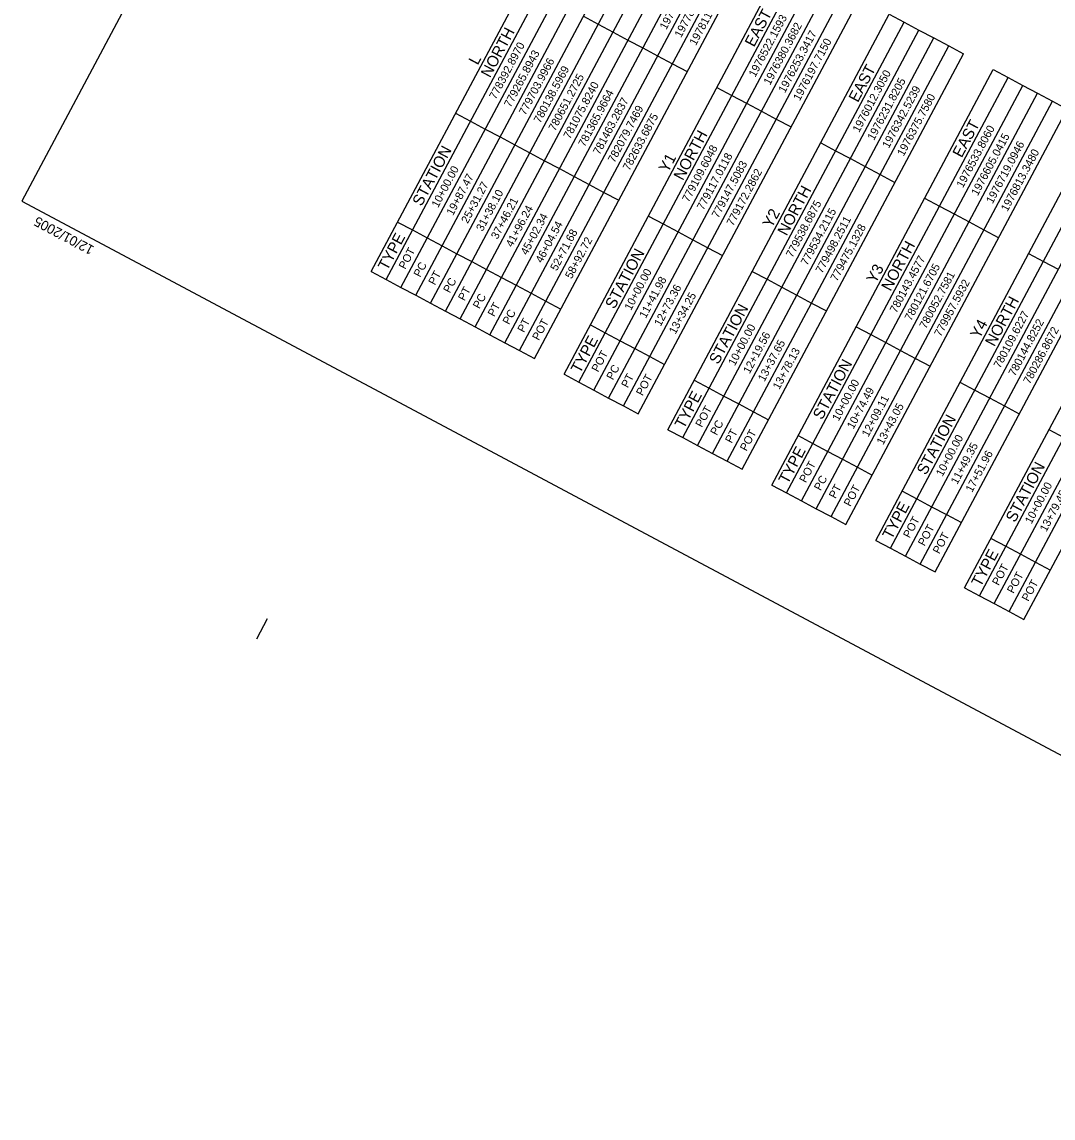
# Model space of a CAD drawing. Extents: x 1979034 to 1987549, y 771535 to 781988.
# Drawn here: x 1979034 to 1981933, y 772365 to 775446 of the extents above; entities that cross this region are included whole.
import ezdxf

# ---------------------------------------------------------------- set-up
doc = ezdxf.new("R2010")
doc.units = 0
for name, color, linetype in [('CTL Sheet Border CELL', 7, 'Continuous'), ('CTL Sheet Notes CELL', 7, 'Continuous'), ('CTL Sheet Table Cell', 7, 'Continuous'), ('CTL Sheet Text', 7, 'Continuous'), ('Sheet Data Field CELL', 7, 'Continuous')]:
    doc.layers.add(name, color=color, linetype=linetype)

msp = doc.modelspace()

# ---------------------------------------------------------------- linework, layer by layer
at = {"layer": 'CTL Sheet Border CELL'}
msp.add_lwpolyline([(1982714.7, 781848.1), (1979034.2, 774941.4), (1983868.8, 772365.1), (1987549.3, 779271.7)], close=True, dxfattribs=at)
at = {"layer": 'CTL Sheet Table Cell'}
for p, q in [((1980016.2, 774744.1), (1980638.4, 775911.6)), ((1980057.9, 774721.8), (1980680.1, 775889.4)), ((1980099.6, 774699.6), (1980721.8, 775867.2)), ((1980141.3, 774677.4), (1980763.5, 775845)), ((1980183, 774655.2), (1980805.2, 775822.8)), ((1980224.7, 774633), (1980846.9, 775800.5)), ((1980266.4, 774610.7), (1980888.6, 775778.3)), ((1980308.1, 774588.5), (1980930.3, 775756.1)), ((1980349.8, 774566.3), (1980972, 775733.9)), ((1980391.5, 774544.1), (1981013.7, 775711.6)), ((1980433.2, 774521.9), (1981055.4, 775689.4)), ((1980474.9, 774499.6), (1981097.1, 775667.2)), ((1980558.3, 774455.2), (1981180.5, 775622.8)), ((1980600, 774433), (1981222.2, 775600.5)), ((1980641.7, 774410.8), (1981263.9, 775578.3)), ((1980683.4, 774388.5), (1981305.6, 775556.1)), ((1980725.1, 774366.3), (1981347.3, 775533.9)), ((1980766.8, 774344.1), (1981389, 775511.7)), ((1980612.6, 775461.4), (1980654.3, 775439.1)), ((1980850.2, 774299.6), (1981472.4, 775467.2)), ((1980891.9, 774277.4), (1981514.1, 775445)), ((1981472.4, 775467.2), (1981514.1, 775445)), ((1981514.1, 775445), (1981555.8, 775422.8)), ((1980654.3, 775439.1), (1980696, 775416.9)), ((1980696, 775416.9), (1980737.7, 775394.7)), ((1980933.6, 774255.2), (1981555.8, 775422.8)), ((1981555.8, 775422.8), (1981597.5, 775400.6)), ((1980737.7, 775394.7), (1980779.4, 775372.5)), ((1980975.3, 774233), (1981597.5, 775400.6)), ((1981597.5, 775400.6), (1981639.2, 775378.3)), ((1980779.4, 775372.5), (1980821.1, 775350.3)), ((1981017, 774210.8), (1981639.2, 775378.3)), ((1981058.7, 774188.5), (1981680.9, 775356.1)), ((1981639.2, 775378.3), (1981680.9, 775356.1)), ((1980821.1, 775350.3), (1980862.8, 775328)), ((1980862.8, 775328), (1980904.5, 775305.8)), ((1981142.1, 774144.1), (1981764.3, 775311.7)), ((1981764.3, 775311.7), (1981806, 775289.4)), ((1980987.9, 775261.4), (1981029.6, 775239.2)), ((1981183.8, 774121.9), (1981806, 775289.4)), ((1981225.5, 774099.7), (1981847.7, 775267.2)), ((1981806, 775289.4), (1981847.7, 775267.2)), ((1981847.7, 775267.2), (1981889.3, 775245)), ((1981029.6, 775239.2), (1981071.3, 775216.9)), ((1981267.2, 774077.4), (1981889.3, 775245)), ((1981889.3, 775245), (1981931, 775222.8)), ((1981071.3, 775216.9), (1981113, 775194.7)), ((1981308.9, 774055.2), (1981931, 775222.8)), ((1981350.6, 774033), (1981972.7, 775200.6)), ((1981931, 775222.8), (1981972.7, 775200.6)), ((1980253.2, 775188.9), (1980294.9, 775166.6)), ((1981113, 775194.7), (1981154.7, 775172.5)), ((1981154.7, 775172.5), (1981196.4, 775150.3)), ((1980294.9, 775166.6), (1980336.6, 775144.4)), ((1980336.6, 775144.4), (1980378.3, 775122.2)), ((1981434, 773988.6), (1982056.1, 775156.1)), ((1980378.3, 775122.2), (1980420, 775100)), ((1981475.7, 773966.3), (1982097.8, 775133.9)), ((1981517.4, 773944.1), (1982139.5, 775111.7)), ((1980420, 775100), (1980461.7, 775077.8)), ((1980461.7, 775077.8), (1980503.4, 775055.5)), ((1981279.8, 775105.8), (1981321.5, 775083.6)), ((1981321.5, 775083.6), (1981363.2, 775061.4)), ((1981559.1, 773921.9), (1982181.2, 775089.5)), ((1980503.4, 775055.5), (1980545.1, 775033.3)), ((1981363.2, 775061.4), (1981404.9, 775039.2)), ((1981600.8, 773899.7), (1982222.9, 775067.2)), ((1980545.1, 775033.3), (1980586.8, 775011.1)), ((1981404.9, 775039.2), (1981446.6, 775016.9)), ((1981446.6, 775016.9), (1981488.3, 774994.7)), ((1981684.1, 773855.2), (1982306.3, 775022.8)), ((1980586.8, 775011.1), (1980628.5, 774988.9)), ((1980628.5, 774988.9), (1980670.2, 774966.6)), ((1981725.8, 773833), (1982348, 775000.6)), ((1980670.2, 774966.6), (1980711.9, 774944.4)), ((1981767.5, 773810.8), (1982389.7, 774978.4)), ((1981809.2, 773788.6), (1982431.4, 774956.1)), ((1981571.7, 774950.3), (1981613.4, 774928.1)), ((1981613.4, 774928.1), (1981655.1, 774905.8)), ((1981850.9, 773766.3), (1982473.1, 774933.9)), ((1980795.3, 774900), (1980837, 774877.8)), ((1981655.1, 774905.8), (1981696.8, 774883.6)), ((1980090.3, 774883.1), (1980132, 774860.8)), ((1980132, 774860.8), (1980173.7, 774838.6)), ((1980837, 774877.8), (1980878.7, 774855.5)), ((1981696.8, 774883.6), (1981738.5, 774861.4)), ((1981738.5, 774861.4), (1981780.2, 774839.2)), ((1980173.7, 774838.6), (1980215.4, 774816.4)), ((1980878.7, 774855.5), (1980920.4, 774833.3)), ((1980920.4, 774833.3), (1980962.1, 774811.1)), ((1980215.4, 774816.4), (1980257.1, 774794.2)), ((1980962.1, 774811.1), (1981003.8, 774788.9)), ((1980257.1, 774794.2), (1980298.8, 774772)), ((1980298.8, 774772), (1980340.5, 774749.7)), ((1981863.6, 774794.7), (1981905.3, 774772.5)), ((1981905.3, 774772.5), (1981947, 774750.3)), ((1980016.2, 774744.1), (1980057.9, 774721.8)), ((1980340.5, 774749.7), (1980382.2, 774727.5)), ((1981087.2, 774744.4), (1981128.9, 774722.2)), ((1980057.9, 774721.8), (1980099.6, 774699.6)), ((1980382.2, 774727.5), (1980423.9, 774705.3)), ((1981128.9, 774722.2), (1981170.6, 774700)), ((1980099.6, 774699.6), (1980141.3, 774677.4)), ((1980141.3, 774677.4), (1980183, 774655.2)), ((1980423.9, 774705.3), (1980465.6, 774683.1)), ((1980465.6, 774683.1), (1980507.3, 774660.9)), ((1981170.6, 774700), (1981212.3, 774677.8)), ((1981212.3, 774677.8), (1981254, 774655.6)), ((1980183, 774655.2), (1980224.7, 774633)), ((1980507.3, 774660.9), (1980549, 774638.6)), ((1981254, 774655.6), (1981295.7, 774633.3)), ((1980224.7, 774633), (1980266.4, 774610.7)), ((1980266.4, 774610.7), (1980308.1, 774588.5)), ((1980308.1, 774588.5), (1980349.8, 774566.3)), ((1980632.4, 774594.2), (1980674, 774572)), ((1981379.1, 774588.9), (1981420.8, 774566.7)), ((1980349.8, 774566.3), (1980391.5, 774544.1)), ((1980674, 774572), (1980715.7, 774549.7)), ((1981420.8, 774566.7), (1981462.5, 774544.4)), ((1980391.5, 774544.1), (1980433.2, 774521.9)), ((1980433.2, 774521.9), (1980474.9, 774499.6)), ((1980715.7, 774549.7), (1980757.4, 774527.5)), ((1980757.4, 774527.5), (1980799.1, 774505.3)), ((1981462.5, 774544.4), (1981504.2, 774522.2)), ((1981504.2, 774522.2), (1981545.9, 774500)), ((1980799.1, 774505.3), (1980840.8, 774483.1)), ((1981545.9, 774500), (1981587.6, 774477.8)), ((1980558.3, 774455.2), (1980600, 774433)), ((1980600, 774433), (1980641.7, 774410.8)), ((1980924.2, 774438.6), (1980965.9, 774416.4)), ((1981671, 774433.3), (1981712.7, 774411.1)), ((1980641.7, 774410.8), (1980683.4, 774388.5)), ((1980965.9, 774416.4), (1981007.6, 774394.2)), ((1981712.7, 774411.1), (1981754.4, 774388.9)), ((1980683.4, 774388.5), (1980725.1, 774366.3)), ((1981007.6, 774394.2), (1981049.3, 774372)), ((1981049.3, 774372), (1981091, 774349.8)), ((1981754.4, 774388.9), (1981796.1, 774366.7)), ((1981796.1, 774366.7), (1981837.8, 774344.5)), ((1980725.1, 774366.3), (1980766.8, 774344.1)), ((1981091, 774349.8), (1981132.7, 774327.5)), ((1980850.2, 774299.6), (1980891.9, 774277.4)), ((1980891.9, 774277.4), (1980933.6, 774255.2)), ((1981216.1, 774283.1), (1981257.8, 774260.9)), ((1981921.2, 774300), (1981962.9, 774277.8)), ((1980933.6, 774255.2), (1980975.3, 774233)), ((1981257.8, 774260.9), (1981299.5, 774238.7)), ((1980975.3, 774233), (1981017, 774210.8)), ((1981299.5, 774238.7), (1981341.2, 774216.4)), ((1981341.2, 774216.4), (1981382.9, 774194.2)), ((1981017, 774210.8), (1981058.7, 774188.5)), ((1981382.9, 774194.2), (1981424.6, 774172)), ((1981142.1, 774144.1), (1981183.8, 774121.9)), ((1981183.8, 774121.9), (1981225.5, 774099.7)), ((1981508, 774127.5), (1981549.7, 774105.3)), ((1981225.5, 774099.7), (1981267.2, 774077.4)), ((1981549.7, 774105.3), (1981591.4, 774083.1)), ((1981267.2, 774077.4), (1981308.9, 774055.2)), ((1981591.4, 774083.1), (1981633.1, 774060.9)), ((1981633.1, 774060.9), (1981674.8, 774038.7)), ((1981308.9, 774055.2), (1981350.6, 774033)), ((1981434, 773988.6), (1981475.7, 773966.3)), ((1981475.7, 773966.3), (1981517.4, 773944.1)), ((1981758.2, 773994.2), (1981799.9, 773972)), ((1981799.9, 773972), (1981841.6, 773949.8)), ((1981517.4, 773944.1), (1981559.1, 773921.9)), ((1981841.6, 773949.8), (1981883.3, 773927.6)), ((1981559.1, 773921.9), (1981600.8, 773899.7)), ((1981883.3, 773927.6), (1981925, 773905.3)), ((1981684.1, 773855.2), (1981725.8, 773833)), ((1981725.8, 773833), (1981767.5, 773810.8)), ((1981767.5, 773810.8), (1981809.2, 773788.6)), ((1981809.2, 773788.6), (1981850.9, 773766.3))]:
    msp.add_line(p, q, dxfattribs=at)
at = {"layer": 'Sheet Data Field CELL'}
msp.add_line((1979694.3, 773711.8), (1979724.9, 773769.3), dxfattribs=at)

# ---------------------------------------------------------------- texts
at = {"layer": 'CTL Sheet Notes CELL'}
for s, p in [('EAST', (1981092, 775373)), ('NORTH', (1980350, 775286.7)), ('L', (1980315.4, 775322.4)), ('EAST', (1981383.9, 775217.4)), ('EAST', (1981675.8, 775061.9)), ('NORTH', (1980892.1, 774997.8)), ('STATION', (1980157.5, 774925.5)), ('Y1', (1980850.2, 775019.7)), ('NORTH', (1981183.9, 774842.3)), ('Y2', (1981142.1, 774864.2)), ('TYPE', (1980061, 774744.5)), ('NORTH', (1981475.8, 774686.7)), ('STATION', (1980699.6, 774636.6)), ('Y3', (1981434, 774708.6)), ('NORTH', (1981767.7, 774531.2)), ('STATION', (1980991.5, 774481.1)), ('Y4', (1981725.9, 774553.1)), ('TYPE', (1980603.1, 774455.6)), ('STATION', (1981283.4, 774325.5)), ('TYPE', (1980895, 774300.1)), ('STATION', (1981575.3, 774170)), ('TYPE', (1981186.9, 774144.5)), ('STATION', (1981825.5, 774036.7)), ('TYPE', (1981478.8, 773989)), ('TYPE', (1981729, 773855.6))]:
    msp.add_text(s, height=31.5, rotation=61.9471, dxfattribs=at).set_placement(p)
at = {"layer": 'CTL Sheet Text'}
for s, p in [('1977585.8266', (1980845.2, 775421.9)), ('1977839.0293', (1980886.9, 775399.6)), ('1978119.8182', (1980928.6, 775377.4)), ('1976522.1593', (1981095.4, 775288.5)), ('1976380.3682', (1981137.1, 775266.3)), ('1976253.3417', (1981178.8, 775244.1)), ('778392.8970', (1980366, 775225.9)), ('1976197.7150', (1981220.5, 775221.9)), ('779265.8943', (1980407.7, 775203.6)), ('779703.9966', (1980449.4, 775181.4)), ('780138.5969', (1980491.1, 775159.2)), ('780651.2725', (1980532.8, 775137)), ('1976012.3050', (1981387.3, 775133)), ('781075.8240', (1980574.5, 775114.8)), ('1976231.8205', (1981429, 775110.8)), ('1976342.5239', (1981470.7, 775088.5)), ('781365.9664', (1980616.2, 775092.5)), ('781463.2837', (1980657.9, 775070.3)), ('1976375.7580', (1981512.4, 775066.3)), ('782079.7469', (1980699.6, 775048.1)), ('782633.6875', (1980741.3, 775025.9)), ('1976533.8060', (1981679.2, 774977.4)), ('1976605.0415', (1981720.9, 774955.2)), ('1976719.0946', (1981762.6, 774933)), ('779109.6048', (1980908.1, 774937)), ('779117.0118', (1980949.8, 774914.8)), ('1976813.3480', (1981804.3, 774910.8)), ('779147.5083', (1980991.5, 774892.5)), ('10+00.00', (1980204, 774921.8)), ('19+87.47', (1980245.7, 774899.6)), ('779172.2862', (1981033.2, 774870.3)), ('25+31.27', (1980287.4, 774877.4)), ('31+38.10', (1980329.1, 774855.2)), ('37+46.21', (1980370.8, 774832.9)), ('41+96.24', (1980412.5, 774810.7)), ('779538.6875', (1981200, 774781.4)), ('779534.2115', (1981241.7, 774759.2)), ('45+02.34', (1980454.2, 774788.5)), ('779498.2511', (1981283.4, 774737)), ('46+04.54', (1980495.9, 774766.3)), ('52+71.68', (1980537.6, 774744.1)), ('779475.1328', (1981325.1, 774714.8)), ('58+92.72', (1980579.3, 774721.8)), ('POT', (1980111.7, 774748.7)), ('PC ', (1980153.4, 774726.5)), ('780143.4577', (1981491.9, 774625.9)), ('780121.6705', (1981533.6, 774603.7)), ('PT ', (1980195.1, 774704.2)), ('10+00.00', (1980746.1, 774632.9)), ('780052.7581', (1981575.3, 774581.5)), ('PC ', (1980236.8, 774682)), ('11+41.98', (1980787.8, 774610.7)), ('12+73.36', (1980829.5, 774588.5)), ('779957.5932', (1981617, 774559.2)), ('PT ', (1980278.5, 774659.8)), ('PC ', (1980320.2, 774637.6)), ('13+34.25', (1980871.2, 774566.3)), ('PT ', (1980361.9, 774615.4)), ('PC ', (1980403.6, 774593.1)), ('PT ', (1980445.3, 774570.9)), ('POT', (1980487, 774548.7)), ('780109.6227', (1981783.8, 774470.3)), ('10+00.00', (1981038, 774477.4)), ('780144.8252', (1981825.5, 774448.1)), ('780286.8672', (1981867.2, 774425.9)), ('12+19.56', (1981079.7, 774455.2)), ('13+37.65', (1981121.4, 774433)), ('POT', (1980653.8, 774459.8)), ('13+78.13', (1981163, 774410.7)), ('PC ', (1980695.5, 774437.6)), ('PT ', (1980737.2, 774415.4)), ('POT', (1980778.9, 774393.1)), ('10+00.00', (1981329.8, 774321.9)), ('10+74.49', (1981371.5, 774299.6)), ('POT', (1980945.7, 774304.3)), ('12+09.11', (1981413.2, 774277.4)), ('13+43.05', (1981454.9, 774255.2)), ('PC ', (1980987.4, 774282)), ('PT ', (1981029.1, 774259.8)), ('POT', (1981070.8, 774237.6)), ('10+00.00', (1981621.7, 774166.3)), ('11+49.35', (1981663.4, 774144.1)), ('POT', (1981237.6, 774148.7)), ('17+51.96', (1981705.1, 774121.9)), ('PC ', (1981279.3, 774126.5)), ('10+00.00', (1981871.9, 774033)), ('PT ', (1981321, 774104.3)), ('POT', (1981362.7, 774082)), ('13+79.45', (1981913.6, 774010.8)), ('POT', (1981529.5, 773993.2)), ('POT', (1981571.2, 773970.9)), ('POT', (1981612.9, 773948.7)), ('POT', (1981779.7, 773859.8)), ('POT', (1981821.4, 773837.6)), ('POT', (1981863.1, 773815.4))]:
    msp.add_text(s, height=22.5, rotation=61.9471, dxfattribs=at).set_placement(p)
at = {"layer": 'Sheet Data Field CELL'}
msp.add_text('12/01/2005', height=27.39, rotation=151.9471, dxfattribs=at).set_placement((1979239.4, 774813.6))

doc.saveas('drawing.dxf')
